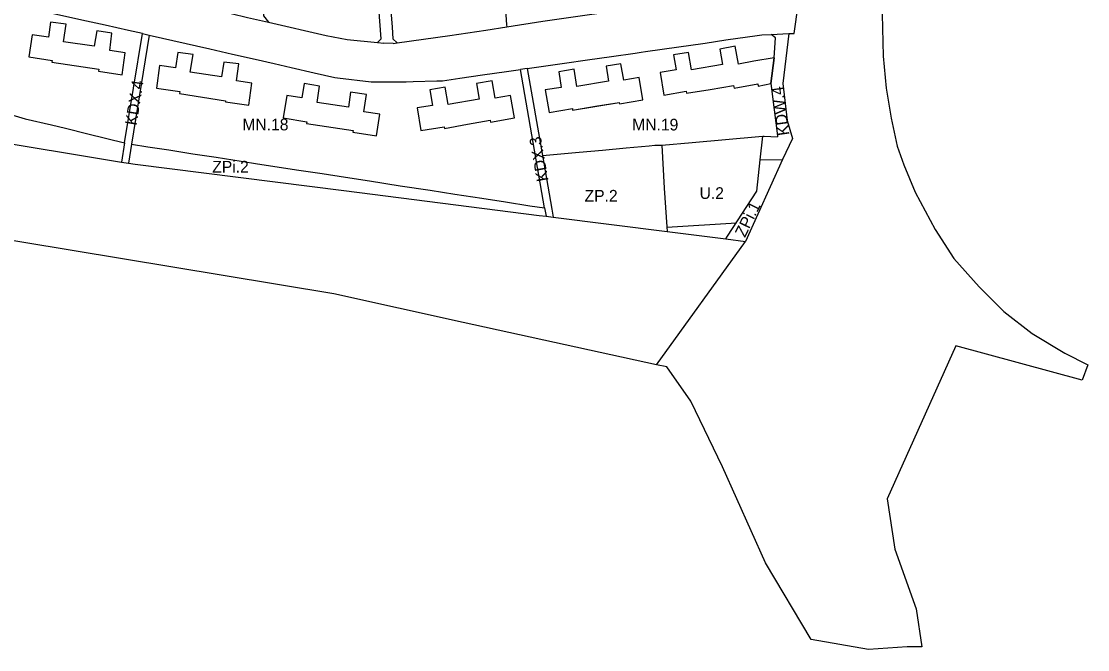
# Model space of a CAD drawing. Extents: x 7419601 to 7420547, y 5548907 to 5549873.
# Drawn here: x 7420033.1 to 7420488.6, y 5548907.3 to 5549175.5 of the extents above; entities that cross this region are included whole.
import ezdxf

# ---------------------------------------------------------------- set-up
doc = ezdxf.new("R2010")
doc.units = 0
for name, color, linetype in [('LIN_linie_rozgraniczajace', 7, 'Continuous'), ('LIN_nieprzekraczalna linia zabudowy', 7, 'Continuous'), ('LIN_obowiązująca linia zabudowy', 7, 'Continuous'), ('TXT_opisy_przeznaczen', 7, 'Continuous')]:
    doc.layers.add(name, color=color, linetype=linetype)

msp = doc.modelspace()

# ---------------------------------------------------------------- linework, layer by layer
at = {"layer": 'LIN_linie_rozgraniczajace'}
for p, q in [((7420087.74, 5549169.66), (7420080.26, 5549123.05)), ((7420084.89, 5549170.3), (7420087.74, 5549169.66)), ((7420191.88, 5549168.04), (7420193.7, 5549166.35)), ((7420360.96, 5549170.26), (7420358.37, 5549148.97)), ((7420192.02, 5549166.12), (7420188, 5549166.25)), ((7420354.66, 5549159.88), (7420353.33, 5549148.96)), ((7420249.28, 5549155.36), (7420246.32, 5549154.94)), ((7420249.28, 5549155.36), (7420255.72, 5549118.23)), ((7420349.89, 5549126.43), (7420349.89, 5549126.43)), ((7420077.26, 5549123.67), (7420075.91, 5549115.43)), ((7420080.26, 5549123.05), (7420078.96, 5549114.93)), ((7420358.32, 5549116.48), (7420342.44, 5549081.58)), ((7420256.65, 5549095.85), (7420257.27, 5549092.33)), ((7420304.45, 5549028.93), (7420342.44, 5549081.58))]:
    msp.add_line(p, q, dxfattribs=at)
for points in [[(7420360.96, 5549170.26), (7420363.21, 5549170.37), (7420376.18, 5549262.27), (7420379.7, 5549288.81), (7420387.03, 5549338.97), (7420384, 5549352.39)], [(7420236.25, 5549249.99), (7420236.45, 5549246.97), (7420236.83, 5549239.86), (7420236.85, 5549239.28), (7420236.93, 5549237.9), (7420237.08, 5549234.89), (7420239.37, 5549189.63), (7420239.49, 5549187), (7420240.38, 5549174), (7420240.47, 5549173.13)], [(7420185.33, 5549166.5), (7420186.88, 5549168.03), (7420184.93, 5549194.71), (7420184.15, 5549209.97), (7420183.36, 5549225.24), (7420182.55, 5549240.59), (7420178.89, 5549242.63), (7420178.89, 5549247.63), (7420178.78, 5549247.66), (7420162.62, 5549246.51), (7420141.87, 5549245.26), (7420138.65, 5549244.31), (7420137.27, 5549243.18), (7420136.57, 5549241.92)], [(7420136.57, 5549241.92), (7420134.61, 5549230.15), (7420135.42, 5549210.09), (7420135.93, 5549197.02), (7420136.56, 5549177.82), (7420138.71, 5549175.15), (7420163.31, 5549169.47)], [(7420187.64, 5549240.97), (7420188.02, 5549231.63), (7420188.8, 5549218.43), (7420189.5, 5549206.03), (7420190.26, 5549193.39), (7420190.99, 5549179.98), (7420191.5, 5549173.05), (7420191.88, 5549168.04)], [(7420084.89, 5549170.3), (7420078.89, 5549171.67), (7420068.95, 5549173.94), (7420058.99, 5549176.05), (7420010.3, 5549186.99), (7419973.64, 5549195.23), (7419934.39, 5549204.06), (7419932.6, 5549204.46)], [(7420083.48, 5549188.06), (7420086.58, 5549187.35), (7420108.79, 5549182.25), (7420129.69, 5549177.2), (7420138.71, 5549175.15)], [(7419933.5, 5549183.94), (7419933.66, 5549180.45), (7419934.25, 5549167.06), (7419941.13, 5549164.7), (7419950.49, 5549161.48), (7419964.74, 5549156.57), (7419974.54, 5549153.21), (7419983.67, 5549150.07), (7419993.3, 5549146.77), (7420002.76, 5549143.52), (7420013.4, 5549140.23), (7420019.71, 5549138.36), (7420025.18, 5549136.74), (7420034.78, 5549133.89), (7420046.03, 5549131.4), (7420052.08, 5549129.9), (7420061.59, 5549127.54), (7420077.26, 5549123.67)], [(7420255.93, 5549175.52), (7420275.89, 5549178.38), (7420298.13, 5549181.4), (7420299.62, 5549181.6)], [(7420231.57, 5549171.77), (7420240.47, 5549173.13), (7420255.93, 5549175.52)], [(7420400.82, 5549178.61), (7420401.26, 5549160.65), (7420402.61, 5549146.95), (7420404.67, 5549134.13), (7420407.32, 5549122.21), (7420410.13, 5549114.21), (7420415.02, 5549102.57), (7420423.46, 5549086.58), (7420431.46, 5549074.21), (7420442.33, 5549062.19), (7420452.88, 5549051.67), (7420464.98, 5549042.29), (7420478.89, 5549033.9), (7420488.65, 5549028.88), (7420486.26, 5549022.37), (7420432.28, 5549036.92), (7420403.04, 5548971.65), (7420406.32, 5548950.17), (7420415.33, 5548924.77), (7420417.81, 5548908.42), (7420411.6, 5548908.46), (7420395.06, 5548907.27), (7420370.54, 5548911.59), (7420351.06, 5548944.32), (7420332.61, 5548985.34), (7420319.16, 5549013.29), (7420308.86, 5549027.97)], [(7420192.02, 5549166.12), (7420193.7, 5549166.35), (7420216.22, 5549169.47), (7420231.57, 5549171.77)], [(7420077.26, 5549123.67), (7420084.89, 5549170.3)], [(7420087.74, 5549169.66), (7420113.7, 5549163.73), (7420123.35, 5549161.52), (7420133.05, 5549159.32), (7420141.09, 5549157.48), (7420148.41, 5549155.81), (7420158.21, 5549153.57), (7420167.02, 5549151.56), (7420168.16, 5549151.41), (7420182.55, 5549149.63), (7420188.44, 5549149.65), (7420194.59, 5549149.68), (7420197.48, 5549149.7), (7420200.52, 5549149.78), (7420210.67, 5549150.06), (7420213.02, 5549150.12), (7420220.43, 5549151.21), (7420230.1, 5549152.61), (7420240.38, 5549154.05), (7420244.32, 5549154.62), (7420246.32, 5549154.94)], [(7420163.31, 5549169.47), (7420172.27, 5549167.73), (7420185.33, 5549166.5), (7420188, 5549166.25)], [(7420249.28, 5549155.36), (7420255.21, 5549156.21), (7420265.18, 5549157.64), (7420275, 5549159.05), (7420285.18, 5549160.52), (7420295.3, 5549161.97), (7420297.88, 5549162.33), (7420299.73, 5549162.6), (7420313.95, 5549164.65), (7420324.2, 5549166.11), (7420325.22, 5549166.26), (7420334.11, 5549167.55), (7420347.51, 5549169.47), (7420349.45, 5549169.75), (7420353.46, 5549169.92), (7420360.96, 5549170.26)], [(7420354.66, 5549159.88), (7420355.26, 5549168.43), (7420353.46, 5549169.92)], [(7420080.26, 5549123.05), (7420087.24, 5549121.97), (7420096.17, 5549120.59), (7420106.46, 5549119.01), (7420116.34, 5549117.49), (7420127.1, 5549115.82), (7420134.08, 5549114.74), (7420151.7, 5549112.03), (7420161.66, 5549110.5), (7420171.59, 5549108.96), (7420181.91, 5549107.38), (7420194.99, 5549105.36), (7420207.83, 5549103.38), (7420218.3, 5549101.76), (7420229.82, 5549099.98), (7420240.01, 5549098.42), (7420250.38, 5549096.82), (7420256.65, 5549095.85), (7420246.32, 5549154.94)], [(7420308.86, 5549027.97), (7420304.45, 5549028.93), (7420221.89, 5549046.98), (7420166.67, 5549059.16), (7420119.38, 5549066.99), (7420011.67, 5549084.81), (7420008.57, 5549085.32), (7419989.25, 5549089.64), (7419923.85, 5549104.28), (7419875.2, 5549119.84), (7419838.22, 5549134.12), (7419802.38, 5549150.01)], [(7420353.33, 5549148.96), (7420354.74, 5549137.79), (7420356.15, 5549126.61), (7420356.2, 5549126.21)], [(7420358.37, 5549148.97), (7420360.35, 5549133.23), (7420362.61, 5549125.53), (7420358.32, 5549116.48)], [(7419924.88, 5549146.43), (7419965.46, 5549135.48), (7420014.97, 5549125.52), (7420075.91, 5549115.43)], [(7420306.68, 5549122.66), (7420319.77, 5549123.84), (7420348.2, 5549126.28)], [(7420334.11, 5549082.63), (7420334.85, 5549083.77), (7420347.37, 5549102.97), (7420348.81, 5549116.4), (7420349.89, 5549126.43)], [(7420348.2, 5549126.28), (7420349.89, 5549126.43)], [(7420349.89, 5549126.43), (7420350.43, 5549126.52), (7420356.2, 5549126.21)], [(7420255.72, 5549118.23), (7420271.43, 5549119.71), (7420281.46, 5549120.57), (7420291.5, 5549121.5), (7420301.37, 5549122.39), (7420303.72, 5549122.61), (7420306.68, 5549122.66)], [(7420306.68, 5549122.66), (7420307.81, 5549104.34), (7420308.84, 5549087.81), (7420308.97, 5549085.8)], [(7420255.72, 5549118.23), (7420259.77, 5549095.37), (7420260.38, 5549091.93)], [(7420348.81, 5549116.4), (7420358.32, 5549116.48)], [(7420075.91, 5549115.43), (7420078.96, 5549114.93)], [(7420078.96, 5549114.93), (7420081.74, 5549114.47), (7420170.86, 5549103.23), (7420254.4, 5549092.69), (7420257.27, 5549092.33)], [(7420257.27, 5549092.33), (7420260.38, 5549091.93)], [(7420260.38, 5549091.93), (7420308.97, 5549085.8)], [(7420308.97, 5549085.8), (7420334.11, 5549082.63)], [(7420334.11, 5549082.63), (7420342.44, 5549081.58)]]:
    msp.add_lwpolyline(points, dxfattribs=at)
at = {"layer": 'LIN_nieprzekraczalna linia zabudowy'}
msp.add_line((7420308.85, 5549087.6), (7420338.63, 5549089.56), dxfattribs=at)
at = {"layer": 'LIN_obowiązująca linia zabudowy'}
for p, q in [((7420045.64, 5549175.19), (7420044.75, 5549168.69)), ((7420052.26, 5549174.27), (7420045.64, 5549175.19)), ((7420051.17, 5549166.83), (7420052.26, 5549174.27)), ((7420065.33, 5549171.43), (7420064.32, 5549164.95)), ((7420071.84, 5549170.48), (7420065.33, 5549171.43)), ((7420037.74, 5549169.76), (7420036.39, 5549160.38)), ((7420044.75, 5549168.69), (7420037.74, 5549169.76)), ((7420064.32, 5549164.95), (7420051.17, 5549166.83)), ((7420070.88, 5549163.01), (7420071.84, 5549170.48)), ((7420077.51, 5549162.08), (7420070.88, 5549163.01)), ((7420076.16, 5549152.61), (7420077.51, 5549162.08)), ((7420099.99, 5549162.27), (7420099, 5549155.67)), ((7420106.51, 5549161.3), (7420099.99, 5549162.27)), ((7420318.08, 5549162.27), (7420311.7, 5549161.25)), ((7420319.35, 5549154.77), (7420318.08, 5549162.27)), ((7420338.12, 5549164.9), (7420331.55, 5549163.69)), ((7420331.55, 5549163.69), (7420332.69, 5549157.16)), ((7420339.52, 5549157.18), (7420338.12, 5549164.9)), ((7420036.39, 5549160.38), (7420046.3, 5549158.83)), ((7420046.3, 5549158.83), (7420046.2, 5549158.07)), ((7420046.2, 5549158.07), (7420066.25, 5549155.13)), ((7420105.3, 5549153.85), (7420106.51, 5549161.3)), ((7420119.6, 5549158.08), (7420118.6, 5549151.84)), ((7420126.02, 5549157.33), (7420119.6, 5549158.08)), ((7420125.07, 5549150.05), (7420126.02, 5549157.33)), ((7420289.21, 5549157.34), (7420282.93, 5549156.38)), ((7420289.21, 5549157.34), (7420282.93, 5549156.38)), ((7420290.44, 5549150.42), (7420289.21, 5549157.34)), ((7420290.44, 5549150.42), (7420289.21, 5549157.34)), ((7420311.7, 5549161.25), (7420312.82, 5549154.85)), ((7420346.08, 5549158.5), (7420339.52, 5549157.18)), ((7420354.66, 5549159.88), (7420346.08, 5549158.5)), ((7420353.33, 5549148.96), (7420354.66, 5549159.88)), ((7420066.25, 5549155.13), (7420066.11, 5549154.18)), ((7420066.11, 5549154.18), (7420076.16, 5549152.61)), ((7420092.23, 5549156.72), (7420090.85, 5549147.05)), ((7420099, 5549155.67), (7420092.23, 5549156.72)), ((7420118.6, 5549151.84), (7420105.3, 5549153.85)), ((7420269.24, 5549155.03), (7420262.75, 5549154.03)), ((7420269.24, 5549155.03), (7420262.75, 5549154.03)), ((7420262.75, 5549154.03), (7420263.68, 5549147.33)), ((7420262.75, 5549154.03), (7420263.68, 5549147.33)), ((7420270.47, 5549147.7), (7420269.24, 5549155.03)), ((7420270.47, 5549147.7), (7420269.24, 5549155.03)), ((7420282.93, 5549156.38), (7420283.93, 5549149.97)), ((7420282.93, 5549156.38), (7420283.93, 5549149.97)), ((7420312.82, 5549154.85), (7420305.99, 5549153.66)), ((7420305.99, 5549153.66), (7420307.66, 5549144.04)), ((7420332.69, 5549157.16), (7420319.35, 5549154.77)), ((7420131.66, 5549149.12), (7420125.07, 5549150.05)), ((7420130.34, 5549139.66), (7420131.66, 5549149.12)), ((7420154.03, 5549148.97), (7420153.02, 5549142.82)), ((7420160.52, 5549147.9), (7420154.03, 5549148.97)), ((7420234.28, 5549150.1), (7420227.55, 5549148.97)), ((7420227.55, 5549148.97), (7420228.69, 5549142.29)), ((7420235.58, 5549142.67), (7420234.28, 5549150.1)), ((7420283.93, 5549149.97), (7420270.47, 5549147.7)), ((7420283.93, 5549149.97), (7420270.47, 5549147.7)), ((7420297.05, 5549151.48), (7420290.44, 5549150.42)), ((7420297.05, 5549151.48), (7420290.44, 5549150.42)), ((7420298.63, 5549142.04), (7420297.05, 5549151.48)), ((7420298.63, 5549142.04), (7420297.05, 5549151.48)), ((7420327.46, 5549146.47), (7420337.38, 5549148.19)), ((7420337.38, 5549148.19), (7420337.58, 5549147)), ((7420337.58, 5549147), (7420347.71, 5549148.87)), ((7420347.71, 5549148.87), (7420347.88, 5549147.84)), ((7420347.88, 5549147.84), (7420353.33, 5549148.96)), ((7420090.85, 5549147.05), (7420100.8, 5549145.63)), ((7420100.8, 5549145.63), (7420100.64, 5549144.74)), ((7420100.64, 5549144.74), (7420120.41, 5549141.64)), ((7420146.55, 5549143.87), (7420145.06, 5549134.34)), ((7420153.02, 5549142.82), (7420146.55, 5549143.87)), ((7420159.57, 5549140.9), (7420160.52, 5549147.9)), ((7420173.82, 5549145.3), (7420172.96, 5549138.84)), ((7420180.61, 5549144.35), (7420173.82, 5549145.3)), ((7420179.49, 5549136.9), (7420180.61, 5549144.35)), ((7420214.23, 5549147.42), (7420207.63, 5549146.25)), ((7420207.63, 5549146.25), (7420208.77, 5549139.6)), ((7420215.47, 5549139.97), (7420214.23, 5549147.42)), ((7420242.16, 5549143.85), (7420235.58, 5549142.67)), ((7420243.84, 5549134.25), (7420242.16, 5549143.85)), ((7420263.68, 5549147.33), (7420256.92, 5549146.24)), ((7420263.68, 5549147.33), (7420256.92, 5549146.24)), ((7420256.92, 5549146.24), (7420258.57, 5549136.66)), ((7420256.92, 5549146.24), (7420258.57, 5549136.66)), ((7420307.66, 5549144.04), (7420317.09, 5549145.69)), ((7420317.09, 5549145.69), (7420317.24, 5549144.79)), ((7420317.24, 5549144.79), (7420327.46, 5549146.47)), ((7420120.41, 5549141.64), (7420120.33, 5549141.11)), ((7420120.33, 5549141.11), (7420130.34, 5549139.66)), ((7420172.96, 5549138.84), (7420159.57, 5549140.9)), ((7420208.77, 5549139.6), (7420202.29, 5549138.54)), ((7420228.69, 5549142.29), (7420215.47, 5549139.97)), ((7420268.64, 5549137.59), (7420288.56, 5549140.89)), ((7420268.64, 5549137.59), (7420278.4, 5549139.28)), ((7420278.4, 5549139.28), (7420288.56, 5549140.89)), ((7420288.56, 5549140.89), (7420288.66, 5549140.33)), ((7420288.56, 5549140.89), (7420288.66, 5549140.33)), ((7420288.66, 5549140.33), (7420298.63, 5549142.04)), ((7420288.66, 5549140.33), (7420298.63, 5549142.04)), ((7420186.32, 5549135.91), (7420179.49, 5549136.9)), ((7420184.89, 5549126.66), (7420186.32, 5549135.91)), ((7420202.29, 5549138.54), (7420203.81, 5549128.93)), ((7420258.57, 5549136.66), (7420268.52, 5549138.32)), ((7420258.57, 5549136.66), (7420268.52, 5549138.32)), ((7420268.52, 5549138.32), (7420268.64, 5549137.59)), ((7420268.52, 5549138.32), (7420268.64, 5549137.59)), ((7420145.06, 5549134.34), (7420155.08, 5549132.62)), ((7420155.08, 5549132.62), (7420154.97, 5549131.89)), ((7420154.97, 5549131.89), (7420174.91, 5549128.92)), ((7420203.81, 5549128.93), (7420213.77, 5549130.53)), ((7420213.77, 5549130.53), (7420213.89, 5549129.8)), ((7420213.89, 5549129.8), (7420223.77, 5549131.55)), ((7420223.77, 5549131.55), (7420233.4, 5549133.28)), ((7420233.4, 5549133.28), (7420233.54, 5549132.45)), ((7420233.54, 5549132.45), (7420243.84, 5549134.25)), ((7420174.91, 5549128.92), (7420174.81, 5549128.23)), ((7420174.81, 5549128.23), (7420184.89, 5549126.66))]:
    msp.add_line(p, q, dxfattribs=at)

# ---------------------------------------------------------------- texts
at = {"layer": 'TXT_opisy_przeznaczen'}
for s, rotation, p in [('KDX.4', 81, (7420082.36, 5549130.85)), ('KDW.4', 97.9011, (7420361.27, 5549127.08)), ('KDX.3', 100, (7420258.35, 5549107.59)), ('ZPi.1', 64.0023, (7420342.24, 5549082.96))]:
    msp.add_text(s, height=5, rotation=rotation, dxfattribs=at).set_placement(p)
for s, p in [('MN.18', (7420127.56, 5549128.96)), ('MN.19', (7420294.09, 5549128.92)), ('ZPi.2', (7420114.69, 5549110.95)), ('ZP.2', (7420273.74, 5549098.55)), ('U.2', (7420322.85, 5549099.69))]:
    msp.add_text(s, height=5, dxfattribs=at).set_placement(p)

doc.saveas('drawing.dxf')
